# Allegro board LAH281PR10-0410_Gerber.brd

Outline 408.35 x 178.1 mm; copper layers: TOP, GND1, IN1, GND2, IN2, GND3, VCC, IN3, GND4, IN4, GND5, BOTTOM. Coordinates in mm from the lower left corner of the outline.
Outline path: 0,77 1.45,77 arc(1.95,77.51) 1.45,78.01 1.45,81.82 5.41,81.82 arc(8.25,79.8) 11.09,81.82 13.19,81.82 arc(24.8,69.33) 39.94,61.48 arc(45.01,60.3) 50.19,59.9 69.22,59.9 arc(75.64,60.51) 81.84,62.33 arc(90.43,66.92) 97.82,73.27 arc(102.94,80.44) 106.05,88.68 106.05,114.06 arc(106.28,114.63) 106.85,114.86 107.01,114.86 arc(107.58,115.09) 107.81,115.66 107.81,130.06 arc(107.58,130.63) 107.01,130.86 106.85,130.86 arc(106.28,131.09) 106.05,131.66 106.05,158.95 arc(106.34,159.66) 107.05,159.95 110.17,159.95 110.17,178.1 112.72,178.1 112.72,166.9 arc(112.22,166.4) 112.72,165.9 126.52,165.9 arc(127.02,166.4) 126.52,166.9 126.52,178.1 129.65,178.1 129.65,175.55 138.65,175.55 138.65,168.25 arc(138.79,167.9) 139.15,167.75 140.5,167.75 140.5,166.72 arc(140.64,166.37) 141,166.22 150.5,166.22 arc(150.85,166.37) 151,166.72 151,167.75 152.35,167.75 arc(152.7,167.9) 152.85,168.25 152.85,175.55 155.85,175.55 155.85,177.1 170.75,177.1 arc(172.16,176.51) 172.75,175.1 172.75,109.19 185.84,96.1 303.08,96.1 arc(321.92,71.36) 350.63,59.41 360.9,59.41 arc(380.33,64.07) 395.53,77.03 406.35,77.03 arc(407.76,76.44) 408.35,75.03 408.35,67.06 arc(408.28,67.05) 408.2,67.05 406.4,67.05 arc(405.7,66.76) 405.4,66.05 405.4,57.95 arc(405.7,57.24) 406.4,56.95 408.2,56.95 arc(408.28,56.95) 408.35,56.94 408.35,54.4 404.98,54.4 404.98,53.27 396.6,53.27 396.6,45.77 404.98,45.77 404.98,44.65 408.35,44.65 408.35,42.11 arc(408.28,42.1) 408.2,42.1 406.4,42.1 arc(405.7,41.81) 405.4,41.1 405.4,33 arc(405.7,32.29) 406.4,32 408.2,32 arc(408.28,32) 408.35,31.99 408.35,10.3 arc(407.76,8.89) 406.35,8.3 398.85,8.3 arc(397.44,7.71) 396.85,6.3 396.85,2 arc(396.26,0.59) 394.85,0 391.34,0 arc(390.14,0.4) 389.42,1.45 arc(388.6,1.99) 387.95,1.25 385.67,1.25 arc(385.62,1.37) 385.6,1.5 385.6,6.51 arc(385.23,6.99) 384.67,6.76 arc(384.48,6.58) 384.23,6.51 365.77,6.51 arc(365.52,6.58) 365.33,6.76 arc(364.77,6.99) 364.4,6.51 364.4,1.5 arc(364.38,1.37) 364.33,1.25 361.95,1.25 arc(361.3,1.99) 360.48,1.45 arc(359.76,0.4) 358.56,0 11.55,0 arc(10.14,0.59) 9.55,2 9.55,4.3 arc(9.26,5.01) 8.55,5.3 6.55,5.3 arc(5.84,5.59) 5.55,6.3 5.55,7 arc(5.26,7.71) 4.55,8 2.2,8 2.2,38.54 3.85,38.54 3.85,43.78 1.45,43.78 1.45,47.91 arc(1.95,48.4) 1.45,48.9 0,48.9 0,50.35 arc(0.02,50.48) 0.07,50.6 0.43,51.24 arc(0.48,51.36) 0.5,51.49 0.5,58.22 arc(0.48,58.35) 0.43,58.47 0.07,59.1 arc(0.02,59.23) 0,59.35 0,60.15 arc(0.15,60.51) 0.5,60.65 1.04,60.65 1.05,60.66 arc(1.5,61.15) 1.05,61.65 1.05,64.26 arc(1.5,64.76) 1.05,65.25 1.04,65.25 0.5,65.25 arc(0.15,65.4) 0,65.76 0,66.55 arc(0.02,66.68) 0.07,66.8 0.43,67.44 arc(0.48,67.56) 0.5,67.69 0.5,74.42 arc(0.48,74.55) 0.43,74.67 0.07,75.3 arc(0.02,75.43) 0,75.55 0,77

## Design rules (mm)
net group +3.3V_EC_PLL: nets +3.3V_EC_PLL +VSS_PLL
net group BC: nets BC_CLK_ECE1117 BC_DAT_ECE1117
net group CCG5_ILIM1#: nets CCG5_ILIM1# N65693414
net group CCG5_ILIM2#: nets CCG5_ILIM2# N65693416
net group CLK_CNV_PTX_DRX_N: nets CLK_CNV_PTX_DRX_N CLK_CNV_PTX_DRX_N_R
net group CLK_CNV_PTX_DRX_P: nets CLK_CNV_PTX_DRX_P CLK_CNV_PTX_DRX_P_R
net group CNV_COEX1: nets CNV_COEX1 WWAN_COEX1
net group CNV_COEX2: nets CNV_COEX2 WWAN_COEX2
net group CNV_COEX3: nets CNV_COEX3 WWAN_COEX3
net group CPU_24MHZ_R_D: nets CPU_24MHZ_R_D CPU_24MHZ_R_D#
net group CSO_1: nets CSON_1 CSOP_1
net group CSS_1: nets CSSN_1 CSSP_1
net group CSS_2: nets CSSN_2 CSSP_2
net group DDR_XDP_WAN_SMBDAT: nets DDR_XDP_WAN_SMBCLK DDR_XDP_WAN_SMBDAT
net group DIFFPAIR18: nets PCH_DPD_CTRL_CLK PCH_DPD_CTRL_DATA
net group DIFFPAIR67: nets PCIE_PRX_DTX_N19 PCIE_PRX_DTX_P19
net group DIFFPAIR68: nets PCIE_PRX_DTX_N20 PCIE_PRX_DTX_P20
net group DIFFPAIR116: nets TBTB_SBU1 TBTB_SBU2
net group DIFFPAIR117: nets TBTA_SBU1 TBTA_SBU2
net group DIFFPAIR123: nets TBT_B_SBU1 TBT_B_SBU2
net group DIFFPAIR125: nets SW_TBT_A_USB20_N2_R SW_TBT_A_USB20_P2_R
net group DIFFPAIR126: nets TBTB_DPSRC_AUX_N_C TBTB_DPSRC_AUX_P_C
net group DIFFPAIR127: nets TBTA_DPSRC_AUX_N_C TBTA_DPSRC_AUX_P_C
net group INT_SPK_L: nets INT_SPK_L+ INT_SPK_L-
net group INT_SPK_R: nets INT_SPK_R+ INT_SPK_R-
net group INT_SPKR_L: nets INT_SPKR_L+ INT_SPKR_L-
net group INT_SPKR_R: nets INT_SPKR_R+ INT_SPKR_R-
net group MEM_SMBDATA: nets MEM_SMBCLK MEM_SMBDATA
net group MSDATA: nets MSCLK MSDATA
net group PCH_DPB_CTRL_DATA: nets PCH_DPB_CTRL_CLK PCH_DPB_CTRL_DATA
net group PCH_DPC_CTRL_CLK: nets PCH_DPC_CTRL_CLK PCH_DPC_CTRL_DATA
net group PCH_SPI_CLK: nets PCH_SPI_CLK PCH_SPI_CLK_R1
net group PCH_SPI_CS#0: nets PCH_SPI_CS#0 PCH_SPI_CS#0_R1
net group PCH_SPI_CS#1: nets PCH_SPI_CS#1 PCH_SPI_CS#1_R1
net group PCH_SPI_D0: nets PCH_SPI_D0 PCH_SPI_D0_R1
net group PCH_SPI_D1: nets PCH_SPI_D1 PCH_SPI_D1_R1
net group PCH_SPI_D2: nets PCH_SPI_D2 PCH_SPI_D2_R1
net group PCH_SPI_D3: nets PCH_SPI_D3 PCH_SPI_D3_R1
net group PCH_XDP_CLK_DN: nets PCH_XDP_CLK_DN PCH_XDP_CLK_DP
net group PCH_XDP_CLK_DN_R: nets PCH_XDP_CLK_DN_R PCH_XDP_CLK_DP_R
net group PCIE_PRX_C_DTX_N6: nets PCIE_PRX_C_DTX_N6 PCIE_PRX_DTX_N6
net group PCIE_PRX_C_DTX_P6: nets PCIE_PRX_C_DTX_P6 PCIE_PRX_DTX_P6
net group PCIE_PRX_C_RD_DTX_17: nets PCIE_PRX_DTX_N17 PCIE_PRX_DTX_P17
net group PCIE_PRX_C_RD_DTX_18: nets PCIE_PRX_DTX_N18 PCIE_PRX_DTX_P18
net group PCIE_PRX_C_RD_DTX_21: nets PCIE_PRX_DTX_N21 PCIE_PRX_DTX_P21
net group PCIE_PRX_C_RD_DTX_22: nets PCIE_PRX_DTX_N22 PCIE_PRX_DTX_P22
net group PCIE_PRX_C_RD_DTX_23: nets PCIE_PRX_DTX_N23 PCIE_PRX_DTX_P23
net group PCIE_PRX_C_RD_DTX_24: nets PCIE_PRX_DTX_N24 PCIE_PRX_DTX_P24
net group PCIE_PTX_C_DRX_N6: nets PCIE_PTX_C_DRX_N6 PCIE_PTX_DRX_N6
net group PCIE_PTX_C_DRX_N9: nets PCIE_PTX_C_DRX_N9 PCIE_PTX_DRX_N9
net group PCIE_PTX_C_DRX_N10: nets PCIE_PTX_C_DRX_N10 PCIE_PTX_DRX_N10
net group PCIE_PTX_C_DRX_N11: nets PCIE_PTX_C_DRX_N11 PCIE_PTX_DRX_N11
net group PCIE_PTX_C_DRX_N12: nets PCIE_PTX_C_DRX_N12 PCIE_PTX_DRX_N12
net group PCIE_PTX_C_DRX_N13: nets PCIE_PTX_C_DRX_N13 PCIE_PTX_DRX_N13
net group PCIE_PTX_C_DRX_N14: nets PCIE_PTX_C_DRX_N14 PCIE_PTX_DRX_N14
net group PCIE_PTX_C_DRX_N15: nets PCIE_PTX_C_DRX_N15 PCIE_PTX_DRX_N15
net group PCIE_PTX_C_DRX_N16: nets PCIE_PTX_C_DRX_N16 PCIE_PTX_DRX_N16
net group PCIE_PTX_C_DRX_N17: nets PCIE_PTX_C_DRX_N17 PCIE_PTX_DRX_N17
net group PCIE_PTX_C_DRX_N18: nets PCIE_PTX_C_DRX_N18 PCIE_PTX_DRX_N18
net group PCIE_PTX_C_DRX_N19: nets PCIE_PTX_C_DRX_N19 PCIE_PTX_DRX_N19
net group PCIE_PTX_C_DRX_N20: nets PCIE_PTX_C_DRX_N20 PCIE_PTX_DRX_N20
net group PCIE_PTX_C_DRX_N21: nets PCIE_PTX_C_DRX_N21 PCIE_PTX_DRX_N21
net group PCIE_PTX_C_DRX_N22: nets PCIE_PTX_C_DRX_N22 PCIE_PTX_DRX_N22
net group PCIE_PTX_C_DRX_N23: nets PCIE_PTX_C_DRX_N23 PCIE_PTX_DRX_N23
net group PCIE_PTX_C_DRX_N24: nets PCIE_PTX_C_DRX_N24 PCIE_PTX_DRX_N24
net group PCIE_PTX_C_DRX_P6: nets PCIE_PTX_C_DRX_P6 PCIE_PTX_DRX_P6
net group PCIE_PTX_C_DRX_P9: nets PCIE_PTX_C_DRX_P9 PCIE_PTX_DRX_P9
net group PCIE_PTX_C_DRX_P10: nets PCIE_PTX_C_DRX_P10 PCIE_PTX_DRX_P10
net group PCIE_PTX_C_DRX_P11: nets PCIE_PTX_C_DRX_P11 PCIE_PTX_DRX_P11
net group PCIE_PTX_C_DRX_P12: nets PCIE_PTX_C_DRX_P12 PCIE_PTX_DRX_P12
net group PCIE_PTX_C_DRX_P13: nets PCIE_PTX_C_DRX_P13 PCIE_PTX_DRX_P13
net group PCIE_PTX_C_DRX_P14: nets PCIE_PTX_C_DRX_P14 PCIE_PTX_DRX_P14
net group PCIE_PTX_C_DRX_P15: nets PCIE_PTX_C_DRX_P15 PCIE_PTX_DRX_P15
net group PCIE_PTX_C_DRX_P16: nets PCIE_PTX_C_DRX_P16 PCIE_PTX_DRX_P16
net group PCIE_PTX_C_DRX_P17: nets PCIE_PTX_C_DRX_P17 PCIE_PTX_DRX_P17
net group PCIE_PTX_C_DRX_P18: nets PCIE_PTX_C_DRX_P18 PCIE_PTX_DRX_P18
net group PCIE_PTX_C_DRX_P19: nets PCIE_PTX_C_DRX_P19 PCIE_PTX_DRX_P19
net group PCIE_PTX_C_DRX_P20: nets PCIE_PTX_C_DRX_P20 PCIE_PTX_DRX_P20
net group PCIE_PTX_C_DRX_P21: nets PCIE_PTX_C_DRX_P21 PCIE_PTX_DRX_P21
net group PCIE_PTX_C_DRX_P22: nets PCIE_PTX_C_DRX_P22 PCIE_PTX_DRX_P22
net group PCIE_PTX_C_DRX_P23: nets PCIE_PTX_C_DRX_P23 PCIE_PTX_DRX_P23
net group PCIE_PTX_C_DRX_P24: nets PCIE_PTX_C_DRX_P24 PCIE_PTX_DRX_P24
net group REFCLK_CNV: nets N65699658 REFCLK_CNV
net group SD_1_D0: nets SD_1_D0 SD_1_D1
net group SD_1_D1_R: nets SD_1_D0_R SD_1_D1_R
net group SML0_SMBDATA: nets SML0_SMBCLK SML0_SMBDATA
net group SML1_SMBDATA: nets SML1_SMBCLK SML1_SMBDATA
net group SR_1: nets SRN_1 SRP_1
net group SW2_DP2_2_AUXN: nets SW2_DP2_2_AUXN SW2_DP2_2_AUXP
net group SW3_DP1_AUXN: nets SW3_DP1_AUXN SW3_DP1_AUXN_C
net group SW3_DP1_AUXP: nets SW3_DP1_AUXP SW3_DP1_AUXP_C
net group SW3_DP1_N0: nets SW3_DP1_N0 SW3_DP1_N0_C
net group SW3_DP1_N1: nets SW3_DP1_N1 SW3_DP1_N1_C
net group SW3_DP1_N2: nets SW3_DP1_N2 SW3_DP1_N2_C
net group SW3_DP1_N3: nets SW3_DP1_N3 SW3_DP1_N3_C
net group SW3_DP1_P0: nets SW3_DP1_P0 SW3_DP1_P0_C
net group SW3_DP1_P1: nets SW3_DP1_P1 SW3_DP1_P1_C
net group SW3_DP1_P2: nets SW3_DP1_P2 SW3_DP1_P2_C
net group SW3_DP1_P3: nets SW3_DP1_P3 SW3_DP1_P3_C
net group SW4_DP2_AUXN: nets SW4_DP2_AUXN SW4_DP2_AUXN_C
net group SW4_DP2_AUXP: nets SW4_DP2_AUXP SW4_DP2_AUXP_C
net group SW4_DP2_N0: nets SW4_DP2_N0 SW4_DP2_N0_C
net group SW4_DP2_N1: nets SW4_DP2_N1 SW4_DP2_N1_C
net group SW4_DP2_N2: nets SW4_DP2_N2 SW4_DP2_N2_C
net group SW4_DP2_N3: nets SW4_DP2_N3 SW4_DP2_N3_C
net group SW4_DP2_P0: nets SW4_DP2_P0 SW4_DP2_P0_C
net group SW4_DP2_P1: nets SW4_DP2_P1 SW4_DP2_P1_C
net group SW4_DP2_P2: nets SW4_DP2_P2 SW4_DP2_P2_C
net group SW4_DP2_P3: nets SW4_DP2_P3 SW4_DP2_P3_C
net group TBT_A_TRX_DTX_N1: nets TBT_A_TRX_DTX_N1 TBT_A_TRX_DTX_N1_R
net group TBT_A_TRX_DTX_N2: nets TBT_A_TRX_DTX_N2 TBT_A_TRX_DTX_N2_R
net group TBT_A_TRX_DTX_P1: nets TBT_A_TRX_DTX_P1 TBT_A_TRX_DTX_P1_R
net group TBT_A_TRX_DTX_P2: nets TBT_A_TRX_DTX_P2 TBT_A_TRX_DTX_P2_R
net group TBT_B_TRX_DTX_N1: nets TBT_B_TRX_DTX_N1 TBT_B_TRX_DTX_N1_R
net group TBT_B_TRX_DTX_N2: nets TBT_B_TRX_DTX_N2 TBT_B_TRX_DTX_N2_R
net group TBT_B_TRX_DTX_P1: nets TBT_B_TRX_DTX_P1 TBT_B_TRX_DTX_P1_R
net group TBT_B_TRX_DTX_P2: nets TBT_B_TRX_DTX_P2 TBT_B_TRX_DTX_P2_R
net group UART2RXD: nets UART2_RXD UART2RXD
net group UART2TXD: nets UART2_TXD UART2TXD
net group USB20_6: nets USB20_N6 USB20_P6
net group XTAL24_IN_R: nets XTAL24_IN_R XTAL24_IN_R1
net group XTAL24_OUT: nets XTAL24_OUT XTAL24_OUT_R1
net group CCG5_SMBCLK: nets CCG5_SMBCLK N65694331 N65695150
net group CCG5_SMBDAT: nets CCG5_SMBDAT N65694363 N65695146
net group CL_SIG: nets PCH_CL_CLK1 PCH_CL_DATA1 PCH_CL_RST1#
net group DDR_A_CLK: nets DDR_A_CLK0 DDR_A_CLK1 DDR_A_CLK2 DDR_A_CLK3 DDR_A_CLK#0 DDR_A_CLK#1 DDR_A_CLK#2 DDR_A_CLK#3
net group DDR_A_CMD: nets DDR_A_ACT# DDR_A_BA0 DDR_A_BA1 DDR_A_BG0 DDR_A_BG1 DDR_A_MA0 DDR_A_MA1 DDR_A_MA2 DDR_A_MA3 DDR_A_MA4 DDR_A_MA5 DDR_A_MA6 DDR_A_MA7 DDR_A_MA8 DDR_A_MA9 DDR_A_MA10 DDR_A_MA11 DDR_A_MA12 DDR_A_MA13 DDR_A_MA14 DDR_A_MA15 DDR_A_MA16 DDR_A_PARITY
net group DDR_A_CTL: nets DDR_A_CKE0 DDR_A_CKE1 DDR_A_CKE2 DDR_A_CKE3 DDR_A_CS#0 DDR_A_CS#1 DDR_A_CS#2 DDR_A_CS#3 DDR_A_ODT0 DDR_A_ODT1 DDR_A_ODT2 DDR_A_ODT3
net group DDR_A_D0: nets DDR_A_D0 DDR_A_D1 DDR_A_D2 DDR_A_D3 DDR_A_D4 DDR_A_D5 DDR_A_D6 DDR_A_D7
net group DDR_A_D1: nets DDR_A_D8 DDR_A_D9 DDR_A_D10 DDR_A_D11 DDR_A_D12 DDR_A_D13 DDR_A_D14 DDR_A_D15
net group DDR_A_D2: nets DDR_A_D16 DDR_A_D17 DDR_A_D18 DDR_A_D19 DDR_A_D20 DDR_A_D21 DDR_A_D22 DDR_A_D23
net group DDR_A_D3: nets DDR_A_D24 DDR_A_D25 DDR_A_D26 DDR_A_D27 DDR_A_D28 DDR_A_D29 DDR_A_D30 DDR_A_D31
net group DDR_A_D4: nets DDR_A_D32 DDR_A_D33 DDR_A_D34 DDR_A_D35 DDR_A_D36 DDR_A_D37 DDR_A_D38 DDR_A_D39
net group DDR_A_D5: nets DDR_A_D40 DDR_A_D41 DDR_A_D42 DDR_A_D43 DDR_A_D44 DDR_A_D45 DDR_A_D46 DDR_A_D47
net group DDR_A_D6: nets DDR_A_D48 DDR_A_D49 DDR_A_D50 DDR_A_D51 DDR_A_D52 DDR_A_D53 DDR_A_D54 DDR_A_D55
net group DDR_A_D7: nets DDR_A_D56 DDR_A_D57 DDR_A_D58 DDR_A_D59 DDR_A_D60 DDR_A_D61 DDR_A_D62 DDR_A_D63
net group DDR_A_DQS: nets DDR_A_DQS0 DDR_A_DQS1 DDR_A_DQS2 DDR_A_DQS3 DDR_A_DQS4 DDR_A_DQS5 DDR_A_DQS6 DDR_A_DQS7 DDR_A_DQS8 DDR_A_DQS#0 DDR_A_DQS#1 DDR_A_DQS#2 DDR_A_DQS#3 DDR_A_DQS#4 DDR_A_DQS#5 DDR_A_DQS#6 DDR_A_DQS#7 DDR_A_DQS#8
net group DDR_A_ECC: nets DDR_A_CB0 DDR_A_CB1 DDR_A_CB2 DDR_A_CB3 DDR_A_CB4 DDR_A_CB5 DDR_A_CB6 DDR_A_CB7
net group DDR_B_CLK: nets DDR_B_CLK0 DDR_B_CLK1 DDR_B_CLK2 DDR_B_CLK3 DDR_B_CLK#0 DDR_B_CLK#1 DDR_B_CLK#2 DDR_B_CLK#3
net group DDR_B_CMD: nets DDR_B_ACT# DDR_B_BA0 DDR_B_BA1 DDR_B_BG0 DDR_B_BG1 DDR_B_MA0 DDR_B_MA1 DDR_B_MA2 DDR_B_MA3 DDR_B_MA4 DDR_B_MA5 DDR_B_MA6 DDR_B_MA7 DDR_B_MA8 DDR_B_MA9 DDR_B_MA10 DDR_B_MA11 DDR_B_MA12 DDR_B_MA13 DDR_B_MA14 DDR_B_MA15 DDR_B_MA16 DDR_B_PARITY
net group DDR_B_CTL: nets DDR_B_CKE0 DDR_B_CKE1 DDR_B_CKE2 DDR_B_CKE3 DDR_B_CS#0 DDR_B_CS#1 DDR_B_CS#2 DDR_B_CS#3 DDR_B_ODT0 DDR_B_ODT1 DDR_B_ODT2 DDR_B_ODT3
net group DDR_B_D0: nets DDR_B_D0 DDR_B_D1 DDR_B_D2 DDR_B_D3 DDR_B_D4 DDR_B_D5 DDR_B_D6 DDR_B_D7
net group DDR_B_D1: nets DDR_B_D8 DDR_B_D9 DDR_B_D10 DDR_B_D11 DDR_B_D12 DDR_B_D13 DDR_B_D14 DDR_B_D15
net group DDR_B_D2: nets DDR_B_D16 DDR_B_D17 DDR_B_D18 DDR_B_D19 DDR_B_D20 DDR_B_D21 DDR_B_D22 DDR_B_D23
net group DDR_B_D3: nets DDR_B_D24 DDR_B_D25 DDR_B_D26 DDR_B_D27 DDR_B_D28 DDR_B_D29 DDR_B_D30 DDR_B_D31
net group DDR_B_D4: nets DDR_B_D32 DDR_B_D33 DDR_B_D34 DDR_B_D35 DDR_B_D36 DDR_B_D37 DDR_B_D38 DDR_B_D39
net group DDR_B_D5: nets DDR_B_D40 DDR_B_D41 DDR_B_D42 DDR_B_D43 DDR_B_D44 DDR_B_D45 DDR_B_D46 DDR_B_D47
net group DDR_B_D6: nets DDR_B_D48 DDR_B_D49 DDR_B_D50 DDR_B_D51 DDR_B_D52 DDR_B_D53 DDR_B_D54 DDR_B_D55
net group DDR_B_D7: nets DDR_B_D56 DDR_B_D57 DDR_B_D58 DDR_B_D59 DDR_B_D60 DDR_B_D61 DDR_B_D62 DDR_B_D63
net group DDR_B_DQS: nets DDR_B_DQS0 DDR_B_DQS1 DDR_B_DQS2 DDR_B_DQS3 DDR_B_DQS4 DDR_B_DQS5 DDR_B_DQS6 DDR_B_DQS7 DDR_B_DQS8 DDR_B_DQS#0 DDR_B_DQS#1 DDR_B_DQS#2 DDR_B_DQS#3 DDR_B_DQS#4 DDR_B_DQS#5 DDR_B_DQS#6 DDR_B_DQS#7 DDR_B_DQS#8
net group DDR_B_ECC: nets DDR_B_CB0 DDR_B_CB1 DDR_B_CB2 DDR_B_CB3 DDR_B_CB4 DDR_B_CB5 DDR_B_CB6 DDR_B_CB7
net group DEMUX_PS8331: nets SW1_EDP_AUXN SW1_EDP_AUXN_C SW1_EDP_AUXP SW1_EDP_AUXP_C SW2_DP2_1_AUXN SW2_DP2_1_AUXN_C SW2_DP2_1_AUXP SW2_DP2_1_AUXP_C SW2_DP2_1_N0 SW2_DP2_1_N0_C SW2_DP2_1_N1 SW2_DP2_1_N1_C SW2_DP2_1_N2 SW2_DP2_1_N2_C SW2_DP2_1_N3 SW2_DP2_1_N3_C SW2_DP2_1_P0 SW2_DP2_1_P0_C SW2_DP2_1_P1 SW2_DP2_1_P1_C SW2_DP2_1_P2 SW2_DP2_1_P2_C SW2_DP2_1_P3 SW2_DP2_1_P3_C SW2_DP2_2_N0 SW2_DP2_2_N1 SW2_DP2_2_N2 SW2_DP2_2_N3 SW2_DP2_2_P0 SW2_DP2_2_P1 SW2_DP2_2_P2 SW2_DP2_2_P3
net group DIFF_CLK: nets CLK_CNV_PRX_DTX_N CLK_CNV_PRX_DTX_P CLK_PCIE_N1 CLK_PCIE_N2 CLK_PCIE_N3 CLK_PCIE_N4 CLK_PCIE_N6 CLK_PCIE_N7 CLK_PCIE_N8 CLK_PCIE_N9 CLK_PCIE_N10 CLK_PCIE_P1 CLK_PCIE_P2 CLK_PCIE_P3 CLK_PCIE_P4 CLK_PCIE_P6 CLK_PCIE_P7 CLK_PCIE_P8 CLK_PCIE_P9 CLK_PCIE_P10 CLK_PEG_N0 CLK_PEG_P0 PCH_CPU_BCLK_D PCH_CPU_BCLK_D# PCH_CPU_BCLK_R_D PCH_CPU_BCLK_R_D# PCH_CPU_NSSC_CLK_D PCH_CPU_NSSC_CLK_D# PCH_CPU_PCIBCLK_D PCH_CPU_PCIBCLK_D# PCH_CPU_PCIBCLK_R_D PCH_CPU_PCIBCLK_R_D#
net group DIFFPAIR115: nets N28153073
net group DMI_RX: nets DMI_CTX_PRX_N0 DMI_CTX_PRX_N1 DMI_CTX_PRX_N2 DMI_CTX_PRX_N3 DMI_CTX_PRX_P0 DMI_CTX_PRX_P1 DMI_CTX_PRX_P2 DMI_CTX_PRX_P3
net group DMI_TX: nets DMI_CRX_PTX_N0 DMI_CRX_PTX_N1 DMI_CRX_PTX_N2 DMI_CRX_PTX_N3 DMI_CRX_PTX_P0 DMI_CRX_PTX_P1 DMI_CRX_PTX_P2 DMI_CRX_PTX_P3
net group EDP: nets EDP_AUXN EDP_AUXN_C EDP_AUXP EDP_AUXP_C EDP_TXN0 EDP_TXN0_C EDP_TXN1 EDP_TXN1_C EDP_TXN2 EDP_TXN2_C EDP_TXN3 EDP_TXN3_C EDP_TXP0 EDP_TXP0_C EDP_TXP1 EDP_TXP1_C EDP_TXP2 EDP_TXP2_C EDP_TXP3 EDP_TXP3_C
net group INTEL_DDI: nets CPU_DP1_AUXN CPU_DP1_AUXN_C CPU_DP1_AUXP CPU_DP1_AUXP_C CPU_DP1_N0 CPU_DP1_N0_C CPU_DP1_N1 CPU_DP1_N1_C CPU_DP1_N2 CPU_DP1_N2_C CPU_DP1_N3 CPU_DP1_N3_C CPU_DP1_P0 CPU_DP1_P0_C CPU_DP1_P1 CPU_DP1_P1_C CPU_DP1_P2 CPU_DP1_P2_C CPU_DP1_P3 CPU_DP1_P3_C CPU_DP2_AUXN CPU_DP2_AUXN_C CPU_DP2_AUXP CPU_DP2_AUXP_C CPU_DP2_N0 CPU_DP2_N0_C CPU_DP2_N1 CPU_DP2_N1_C CPU_DP2_N2 CPU_DP2_N2_C CPU_DP2_N3 CPU_DP2_N3_C CPU_DP2_P0 CPU_DP2_P0_C CPU_DP2_P1 CPU_DP2_P1_C CPU_DP2_P2 CPU_DP2_P2_C CPU_DP2_P3 CPU_DP2_P3_C CPU_DP3_AUXN CPU_DP3_AUXP CPU_DP3_N0 CPU_DP3_N1 CPU_DP3_N2 CPU_DP3_N3 CPU_DP3_P0 CPU_DP3_P1 CPU_DP3_P2 CPU_DP3_P3
net group LAN: nets LAN_MDIN0 LAN_MDIN0_L LAN_MDIN1 LAN_MDIN1_L LAN_MDIN2 LAN_MDIN2_L LAN_MDIN3 LAN_MDIN3_L LAN_MDIP0 LAN_MDIP0_L LAN_MDIP1 LAN_MDIP1_L LAN_MDIP2 LAN_MDIP2_L LAN_MDIP3 LAN_MDIP3_L
net group LAN-NOREF: nets RJ45_MDIN0 RJ45_MDIN1 RJ45_MDIN2 RJ45_MDIN3 RJ45_MDIP0 RJ45_MDIP1 RJ45_MDIP2 RJ45_MDIP3
net group MUXPSB331: nets SW1_EDP_N0 SW1_EDP_N0_C SW1_EDP_N1 SW1_EDP_N1_C SW1_EDP_N2 SW1_EDP_N2_C SW1_EDP_N3 SW1_EDP_N3_C SW1_EDP_P0 SW1_EDP_P1 SW1_EDP_P1_C SW1_EDP_P2 SW1_EDP_P2_C SW1_EDP_P3 SW1_EDP_P3_C
net group MXM_DDI: nets GPU_DP1_AUXN GPU_DP1_AUXP GPU_DP1_C_AUXN GPU_DP1_C_AUXP GPU_DP1_N0 GPU_DP1_N0_C GPU_DP1_N1 GPU_DP1_N1_C GPU_DP1_N2 GPU_DP1_N2_C GPU_DP1_N3 GPU_DP1_N3_C GPU_DP1_P0 GPU_DP1_P0_C GPU_DP1_P1 GPU_DP1_P1_C GPU_DP1_P2 GPU_DP1_P2_C GPU_DP1_P3 GPU_DP1_P3_C GPU_DP2_AUXN GPU_DP2_AUXP GPU_DP2_C_AUXN GPU_DP2_C_AUXP GPU_DP2_N0 GPU_DP2_N0_C GPU_DP2_N1 GPU_DP2_N1_C GPU_DP2_N2 GPU_DP2_N2_C GPU_DP2_N3 GPU_DP2_N3_C GPU_DP2_P0 GPU_DP2_P0_C GPU_DP2_P1 GPU_DP2_P1_C GPU_DP2_P2 GPU_DP2_P2_C GPU_DP2_P3 GPU_DP2_P3_C GPU_EDP_AUXN GPU_EDP_AUXN_C GPU_EDP_AUXP GPU_EDP_AUXP_C GPU_EDP_N0 GPU_EDP_N0_C GPU_EDP_N1 GPU_EDP_N1_C GPU_EDP_N2 GPU_EDP_N2_C GPU_EDP_N3 GPU_EDP_N3_C GPU_EDP_P0 GPU_EDP_P0_C GPU_EDP_P1 GPU_EDP_P1_C GPU_EDP_P2 GPU_EDP_P2_C GPU_EDP_P3 GPU_EDP_P3_C
net group OTHER: nets CPU_2_PCH_TRIGGER_R H_CATERR# H_PWRGD H_THERMTRIP# PCH_2_CPU_TRIGGER PLTRST_CPU# PROCHOT# VCCST_PWRGD
net group PCH_PLTRST#: nets PCH_PLTRST# PLTRST_GPU# PLTRST_LAN# PLTRST_TPM#
net group PCIE_RX: nets PCIE_PRX_C_DTX_N5 PCIE_PRX_C_DTX_P5 PCIE_PRX_C_TTX_N1 PCIE_PRX_C_TTX_N2 PCIE_PRX_C_TTX_N3 PCIE_PRX_C_TTX_N4 PCIE_PRX_C_TTX_P1 PCIE_PRX_C_TTX_P2 PCIE_PRX_C_TTX_P3 PCIE_PRX_C_TTX_P4 PCIE_PRX_DTX_N5 PCIE_PRX_DTX_N7 PCIE_PRX_DTX_N8 PCIE_PRX_DTX_N10 PCIE_PRX_DTX_N11 PCIE_PRX_DTX_N12 PCIE_PRX_DTX_N14 PCIE_PRX_DTX_N15 PCIE_PRX_DTX_N16 PCIE_PRX_DTX_P5 PCIE_PRX_DTX_P7 PCIE_PRX_DTX_P8 PCIE_PRX_DTX_P10 PCIE_PRX_DTX_P11 PCIE_PRX_DTX_P12 PCIE_PRX_DTX_P14 PCIE_PRX_DTX_P15 PCIE_PRX_DTX_P16 PCIE_PRX_TTX_N1 PCIE_PRX_TTX_N2 PCIE_PRX_TTX_N3 PCIE_PRX_TTX_N4 PCIE_PRX_TTX_P1 PCIE_PRX_TTX_P2 PCIE_PRX_TTX_P3 PCIE_PRX_TTX_P4 PCIE_PTX_C_DRX_N5 PCIE_PTX_C_DRX_N7 PCIE_PTX_C_DRX_N8 PCIE_PTX_C_DRX_P5 PCIE_PTX_C_DRX_P7 PCIE_PTX_C_DRX_P8 PCIE_PTX_C_TRX_N1 PCIE_PTX_C_TRX_N2 PCIE_PTX_C_TRX_N3 PCIE_PTX_C_TRX_N4 PCIE_PTX_C_TRX_P1 PCIE_PTX_C_TRX_P2 PCIE_PTX_C_TRX_P3 PCIE_PTX_C_TRX_P4 PCIE_PTX_DRX_N5 PCIE_PTX_DRX_N7 PCIE_PTX_DRX_N8 PCIE_PTX_DRX_P5 PCIE_PTX_DRX_P7 PCIE_PTX_DRX_P8 PCIE_PTX_TRX_N1 PCIE_PTX_TRX_N2 PCIE_PTX_TRX_N3 PCIE_PTX_TRX_N4 PCIE_PTX_TRX_P1 PCIE_PTX_TRX_P2 PCIE_PTX_TRX_P3 PCIE_PTX_TRX_P4
net group PEG_RX: nets PEG_CTX_C_GRX_N0 PEG_CTX_C_GRX_N1 PEG_CTX_C_GRX_N2 PEG_CTX_C_GRX_N3 PEG_CTX_C_GRX_N4 PEG_CTX_C_GRX_N5 PEG_CTX_C_GRX_N6 PEG_CTX_C_GRX_N7 PEG_CTX_C_GRX_N8 PEG_CTX_C_GRX_N9 PEG_CTX_C_GRX_N10 PEG_CTX_C_GRX_N11 PEG_CTX_C_GRX_N12 PEG_CTX_C_GRX_N13 PEG_CTX_C_GRX_N14 PEG_CTX_C_GRX_N15 PEG_CTX_C_GRX_P0 PEG_CTX_C_GRX_P1 PEG_CTX_C_GRX_P2 PEG_CTX_C_GRX_P3 PEG_CTX_C_GRX_P4 PEG_CTX_C_GRX_P5 PEG_CTX_C_GRX_P6 PEG_CTX_C_GRX_P7 PEG_CTX_C_GRX_P8 PEG_CTX_C_GRX_P9 PEG_CTX_C_GRX_P10 PEG_CTX_C_GRX_P11 PEG_CTX_C_GRX_P12 PEG_CTX_C_GRX_P13 PEG_CTX_C_GRX_P14 PEG_CTX_C_GRX_P15 PEG_CTX_GRX_N0 PEG_CTX_GRX_N1 PEG_CTX_GRX_N2 PEG_CTX_GRX_N3 PEG_CTX_GRX_N4 PEG_CTX_GRX_N5 PEG_CTX_GRX_N6 PEG_CTX_GRX_N7 PEG_CTX_GRX_N8 PEG_CTX_GRX_N9 PEG_CTX_GRX_N10 PEG_CTX_GRX_N11 PEG_CTX_GRX_N12 PEG_CTX_GRX_N13 PEG_CTX_GRX_N14 PEG_CTX_GRX_N15 PEG_CTX_GRX_P0 PEG_CTX_GRX_P1 PEG_CTX_GRX_P2 PEG_CTX_GRX_P3 PEG_CTX_GRX_P4 PEG_CTX_GRX_P5 PEG_CTX_GRX_P6 PEG_CTX_GRX_P7 PEG_CTX_GRX_P8 PEG_CTX_GRX_P9 PEG_CTX_GRX_P10 PEG_CTX_GRX_P11 PEG_CTX_GRX_P12 PEG_CTX_GRX_P13 PEG_CTX_GRX_P14 PEG_CTX_GRX_P15
net group PEG_TX: nets PEG_CRX_C_GTX_N0 PEG_CRX_C_GTX_N1 PEG_CRX_C_GTX_N2 PEG_CRX_C_GTX_N3 PEG_CRX_C_GTX_N4 PEG_CRX_C_GTX_N5 PEG_CRX_C_GTX_N6 PEG_CRX_C_GTX_N7 PEG_CRX_C_GTX_N8 PEG_CRX_C_GTX_N9 PEG_CRX_C_GTX_N10 PEG_CRX_C_GTX_N11 PEG_CRX_C_GTX_N12 PEG_CRX_C_GTX_N13 PEG_CRX_C_GTX_N14 PEG_CRX_C_GTX_N15 PEG_CRX_C_GTX_P0 PEG_CRX_C_GTX_P1 PEG_CRX_C_GTX_P2 PEG_CRX_C_GTX_P3 PEG_CRX_C_GTX_P4 PEG_CRX_C_GTX_P5 PEG_CRX_C_GTX_P6 PEG_CRX_C_GTX_P7 PEG_CRX_C_GTX_P8 PEG_CRX_C_GTX_P9 PEG_CRX_C_GTX_P10 PEG_CRX_C_GTX_P11 PEG_CRX_C_GTX_P12 PEG_CRX_C_GTX_P13 PEG_CRX_C_GTX_P14 PEG_CRX_C_GTX_P15 PEG_CRX_GTX_N0 PEG_CRX_GTX_N1 PEG_CRX_GTX_N2 PEG_CRX_GTX_N3 PEG_CRX_GTX_N4 PEG_CRX_GTX_N5 PEG_CRX_GTX_N6 PEG_CRX_GTX_N7 PEG_CRX_GTX_N8 PEG_CRX_GTX_N9 PEG_CRX_GTX_N10 PEG_CRX_GTX_N11 PEG_CRX_GTX_N12 PEG_CRX_GTX_N13 PEG_CRX_GTX_N14 PEG_CRX_GTX_N15 PEG_CRX_GTX_P0 PEG_CRX_GTX_P1 PEG_CRX_GTX_P2 PEG_CRX_GTX_P3 PEG_CRX_GTX_P4 PEG_CRX_GTX_P5 PEG_CRX_GTX_P6 PEG_CRX_GTX_P7 PEG_CRX_GTX_P8 PEG_CRX_GTX_P9 PEG_CRX_GTX_P10 PEG_CRX_GTX_P11 PEG_CRX_GTX_P12 PEG_CRX_GTX_P13 PEG_CRX_GTX_P14 PEG_CRX_GTX_P15
net group POWER: nets +0.6V_P +0.9V_LAN +1.2V_RUN_PWR +3.3V_SSD3_PWR +3.3V_SSD4_PWR +3.3V_SSD5_PWR +3.3V_SSD6_PWR +3.3V_TBT +5V_ALWP +5V_USB_PWR1 +5V_USB_PWR2 +5V_USB_PWR3 +5V_VBUS1 +5V_VBUS2 +19VB_1.2V +19VB_1V +19VB_3V +19VB_3VR +19VB_5V +19VB_5VR +19VB_IO +DGFF_PWR_SRC +VCC_SFR_OC LX_1.2V LX_+1VSP LX_CHG VDD12_A VDD12_B VDD33_A VDD33_B VDD_1.2V VDDA12_A VDDA12_B VDDP_1.2V VDDRX12_A VDDRX12_B VDDTX12_A VDDTX12_B
net group RTC_SIG: nets PCH_RTCRST# PCH_RTCX1 PCH_RTCX1_R PCH_RTCX2 SRTCRST#
net group S15: nets REM_DIODE1_N REM_DIODE1_P REM_DIODE2_N REM_DIODE2_P REM_DIODE3_N REM_DIODE3_P REM_DIODE4_N REM_DIODE4_P
net group SATA: nets PCIE_PRX_DTX_N9 PCIE_PRX_DTX_N13 PCIE_PRX_DTX_P9 PCIE_PRX_DTX_P13
net group SD: nets SD_1_CD# SD_1_CLK SD_1_CLK_R SD_1_CMD SD_1_CMD_R SD_1_D2 SD_1_D2_R SD_1_D3 SD_1_D3_R SDWP_Q
net group SD-DIFF: nets SD_1_N0 SD_1_N1 SD_1_P0 SD_1_P1
net group SPI: nets PCH_SPI_CLK_0_R PCH_SPI_CLK_1_R PCH_SPI_CLK_2_R PCH_SPI_CS#0_R2 PCH_SPI_CS#2 PCH_SPI_CS#2_R PCH_SPI_D0_0_R PCH_SPI_D0_2_R PCH_SPI_D1_0_R PCH_SPI_D1_2_R PCH_SPI_D2_0_R PCH_SPI_D2_XDP PCH_SPI_D3_0_R
net group SW1_EDP_N0_C: nets SW1_EDP_P0_C
net group TBT-A: nets TBT_A_TTX_C_DRX_N1 TBT_A_TTX_C_DRX_N2 TBT_A_TTX_C_DRX_P1 TBT_A_TTX_C_DRX_P2 TBT_A_TTX_DRX_N1 TBT_A_TTX_DRX_N2 TBT_A_TTX_DRX_P1 TBT_A_TTX_DRX_P2
net group TBT-ADIFF: nets SW_TBT_A_USB20_N1 SW_TBT_A_USB20_N1_R SW_TBT_A_USB20_N2 SW_TBT_A_USB20_P1 SW_TBT_A_USB20_P1_R SW_TBT_A_USB20_P2 TBT_A_SBU1 TBT_A_SBU2
net group TBT-B: nets TBT_B_TTX_C_DRX_N1 TBT_B_TTX_C_DRX_N2 TBT_B_TTX_C_DRX_P1 TBT_B_TTX_C_DRX_P2 TBT_B_TTX_DRX_N1 TBT_B_TTX_DRX_N2 TBT_B_TTX_DRX_P1 TBT_B_TTX_DRX_P2
net group TBT-BDIFF: nets SW_TBT_B_USB20_N1 SW_TBT_B_USB20_N1_R SW_TBT_B_USB20_N2 SW_TBT_B_USB20_N2_R SW_TBT_B_USB20_P1 SW_TBT_B_USB20_P1_R SW_TBT_B_USB20_P2 SW_TBT_B_USB20_P2_R
net group TBT_A_USB20N: nets TBT_A_USB20N USB20_N4 USB20_NA
net group TBT_A_USB20P: nets TBT_A_USB20P USB20_P4 USB20_PA
net group TBT_B_USB20N: nets TBT_B_USB20N USB20_N5 USB20_NB
net group TBT_B_USB20P: nets TBT_B_USB20P USB20_P5 USB20_PB
net group USB2: nets CHR_USB20_N1 CHR_USB20_N2 CHR_USB20_N3 CHR_USB20_P1 CHR_USB20_P2 CHR_USB20_P3 USB20_N1 USB20_N1_R USB20_N2 USB20_N2_R USB20_N3 USB20_N3_R USB20_N8 USB20_N10 USB20_N11 USB20_N11_R USB20_N14 USB20_N14_R USB20_P1 USB20_P1_R USB20_P2 USB20_P2_R USB20_P3 USB20_P3_R USB20_P8 USB20_P10 USB20_P11 USB20_P11_R USB20_P14 USB20_P14_R
net group USB3: nets USB3_PRX_C_RD_DTX_N1 USB3_PRX_C_RD_DTX_N3 USB3_PRX_C_RD_DTX_P1 USB3_PRX_C_RD_DTX_P3 USB3_PRX_DTX_N1 USB3_PRX_DTX_N2 USB3_PRX_DTX_N3 USB3_PRX_DTX_N4 USB3_PRX_DTX_P1 USB3_PRX_DTX_P2 USB3_PRX_DTX_P3 USB3_PRX_DTX_P4 USB3_PRX_L_DTX_N2 USB3_PRX_L_DTX_P2 USB3_PRX_RD_DTX_N1 USB3_PRX_RD_DTX_N3 USB3_PRX_RD_DTX_P1 USB3_PRX_RD_DTX_P3 USB3_PTX_C_DRX_N1 USB3_PTX_C_DRX_N2 USB3_PTX_C_DRX_N3 USB3_PTX_C_DRX_N4 USB3_PTX_C_DRX_P1 USB3_PTX_C_DRX_P2 USB3_PTX_C_DRX_P3 USB3_PTX_C_DRX_P4 USB3_PTX_C_RD_DRX_N1 USB3_PTX_C_RD_DRX_N3 USB3_PTX_C_RD_DRX_P1 USB3_PTX_C_RD_DRX_P3 USB3_PTX_DRX_N1 USB3_PTX_DRX_N2 USB3_PTX_DRX_N3 USB3_PTX_DRX_N4 USB3_PTX_DRX_P1 USB3_PTX_DRX_P2 USB3_PTX_DRX_P3 USB3_PTX_DRX_P4 USB3_PTX_L_DRX_N2 USB3_PTX_L_DRX_P2 USB3_PTX_RD_DRX_N1 USB3_PTX_RD_DRX_N3 USB3_PTX_RD_DRX_P1 USB3_PTX_RD_DRX_P3
net group WLAN: nets CNV_PRX_DTX_N0 CNV_PRX_DTX_N1 CNV_PRX_DTX_P0 CNV_PRX_DTX_P1 CNV_PTX_C_DRX_N0 CNV_PTX_C_DRX_N1 CNV_PTX_C_DRX_P0 CNV_PTX_C_DRX_P1 CNV_PTX_DRX_N0 CNV_PTX_DRX_N1 CNV_PTX_DRX_P0 CNV_PTX_DRX_P1
nets with their own width: min track width 0.14; nets DDR_A_DRAMRST# DDR_B_DRAMRST#
nets with their own width: min track width 0.254; nets +RTC_CELL_VBAT
nets with their own width: min track width 0.305; nets DDR_RCOMP0 DDR_RCOMP1 DDR_RCOMP2
nets with their own width: min track width 0.381; nets +1.0V_AZPLL
nets with their own width: min track width 0.508; nets +3.3V_ALW_R +3.3V_SPI +DDR_VREF_B_DQ +V_DDR_REFCA_A +V_DDR_REFCA_B

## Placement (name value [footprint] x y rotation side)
C190  10U_0402_6.3V6M  [C_0402]  144.17 104.66 180 top
C191  10U_0402_6.3V6M  [C_0402]  167.02 134.84 270 bottom
C192  470P_0402_50V7K  [C_0402]  148.51 107.23 270 top
C193  470P_0402_50V7K  [C_0402]  147.62 107.23 270 top
C194  10U_0402_6.3V6M  [C_0402]  151.83 104.28 0 top
C195  470P_0402_50V7K  [C_0402]  168.14 135.5 270 bottom
C199  10U_0402_6.3V6M  [C_0402]  128.09 85.09 90 bottom
C200  10U_0402_6.3V6M  [C_0402]  331.61 17.29 0 top
C201  470P_0402_50V7K  [C_0402]  329.69 20.46 0 top
C202  470P_0402_50V7K  [C_0402]  329.69 19.45 0 top
C203  10U_0402_6.3V6M  [C_0402]  332.74 22.24 0 top
C206  10U_0402_6.3V6M  [C_0402]  353.72 10.56 180 bottom
C207  470P_0402_50V7K  [C_0402]  355.47 13.6 0 bottom
C209  470P_0402_50V7K  [C_0402]  126.96 85.24 90 bottom
CA1  220P_0402_50V8J  [C_0402]  389.58 15.05 90 bottom
CA2  680P_0402_50V7K  [C_0402]  394.24 23 90 bottom
CA3  680P_0402_50V7K  [C_0402]  394.24 25.69 270 bottom
CA4  220P_0402_50V8J  [C_0402]  389.58 17.08 90 bottom
CA8  0.1U_0201_10V6K  [C_0201]  383.32 28.84 0 top
CA9  10U_0603_10V6M  [C_0603]  383.55 30.75 0 top
CA10  0.1U_0201_10V6K  [C_0201]  376.76 19.23 270 top
CA12  680P_0402_50V7K  [C_0402]  392.5 15.97 270 bottom
CA13  680P_0402_50V7K  [C_0402]  392.5 17.72 90 bottom
CA19  1000P_0402_50V7K  [C_0402]  350.01 21.95 0 top
CA22  1000P_0402_50V7K  [C_0402]  346.16 21.9 0 top
CA23  1000P_0402_50V7K  [C_0402]  345.3 21.9 180 top
CA24  1000P_0402_50V7K  [C_0402]  349.15 21.95 180 top
CA25  10U_0603_10V6M  [C_0603]  388.25 23.89 180 top
CA27  0.1U_0201_25V6K  [C_0201]  387.75 26.68 180 top
CA28  0.1U_0201_25V6K  [C_0201]  387.75 25.8 180 top
CA29  1U_0201_6.3V6K  [C_0201]  385.49 17.54 180 top
CA31  1U_0201_6.3V6M  [C_0201]  376.95 28.69 270 top
CA33  10P_0402_50V8J  [C_0402]  377.73 17.02 90 top
CA35  2.2U_0402_6.3V6M  [C_0402]  386.27 30.08 270 bottom
CA41  0.1U_0201_25V6K  [C_0201]  391.49 19.48 270 bottom
CA43  10U_0603_10V6M  [C_0603]  386.85 29.1 0 top
CA44  10U_0603_10V6M  [C_0603]  386.85 27.83 0 top
CA45  0.1U_0201_10V6K  [C_0201]  382.34 25.96 270 bottom
CA46  10U_0603_10V6M  [C_0603]  381.2 31.49 90 top
CA47  0.1U_0201_10V6K  [C_0201]  380.31 25.83 270 bottom
CA48  10U_0603_10V6M  [C_0603]  381.05 30.41 0 top
CA49  1U_0201_6.3V6K  [C_0201]  387.21 19.64 180 top
CA51  10U_0603_10V6M  [C_0603]  384.82 29.62 270 top
CA52  10U_0603_10V6M  [C_0603]  383.49 16.21 90 top
CA53  10U_0603_10V6M  [C_0603]  381.07 16.46 90 top
CA54  68P_0402_50V8J  [C_0402]  374.8 22.24 180 top
CA55  0.1U_0201_10V6K  [C_0201]  377.37 25.4 90 top
CA56  10U_0603_10V6M  [C_0603]  378.14 27.39 90 top
CA57  0.1U_0201_10V6K  [C_0201]  382.56 15.38 0 top
CA58  10U_0603_10V6M  [C_0603]  382.15 14.37 0 top
CA59  10U_0603_10V6M  [C_0603]  378.72 32.78 0 top
CA60  0.1U_0201_10V6K  [C_0201]  378.88 31.89 0 top
CA61  10U_0603_10V6M  [C_0603]  376.76 20.14 90 top
CA63  12P_0402_50V8J  [C_0402]  375.83 30.66 270 top
CA64  68P_0402_50V8J  [C_0402]  376.73 30.66 270 top
CA65  12P_0402_50V8J  [C_0402]  374.72 17.59 90 top
CA66  68P_0402_50V8J  [C_0402]  373.83 17.59 90 top
CA67  12P_0402_50V8J  [C_0402]  392.17 13.73 0 bottom
CA68  68P_0402_50V8J  [C_0402]  392.17 12.84 0 bottom
CA69  33P_0402_50V8J  [C_0402]  382.16 17.55 270 top
CA73  2P_0402_50V8C  [C_0402]  117.63 45.05 180 top
CA74  2P_0402_50V8C  [C_0402]  119.97 42.86 180 top
CA76  2P_0402_50V8C  [C_0402]  120.01 43.75 180 top
CA224  330P_0402_50V8J  [C_0402]  386.46 21.48 0 bottom
CA225  330P_0402_50V8J  [C_0402]  386.46 20.59 0 bottom
CA226  0.1U_0201_25V6K  [C_0201]  374.83 24.65 180 top
CA227  100P_0402_50V8J  [C_0402]  389.46 26.07 0 bottom
CA228  100P_0402_50V8J  [C_0402]  389.56 27.94 0 top
CA232  1U_0201_6.3V6K  [C_0201]  385.49 16.91 180 top
CA233  1U_0201_6.3V6K  [C_0201]  387.21 19.06 180 top
CC28  0.1U_0402_25V6  [C_0402]  243.54 13.47 180 bottom
CC29  0.1U_0402_25V6  [C_0402]  245.84 21.34 90 bottom
CC32  0.1U_0402_25V6  [C_0402]  243.3 21.47 90 bottom
CC33  0.1U_0402_25V6  [C_0402]  232.17 14.68 0 top
CC34  0.22U_0402_16V7K  [C_0402]  253.38 75.24 90 top
CC35  0.22U_0402_16V7K  [C_0402]  252.49 75.24 90 top
CC36  0.22U_0402_16V7K  [C_0402]  251.28 77.19 90 top
CC37  0.22U_0402_16V7K  [C_0402]  252.18 77.19 90 top
CC38  0.22U_0402_16V7K  [C_0402]  250.94 75.24 90 top
CC39  0.22U_0402_16V7K  [C_0402]  250.05 75.24 90 top
CC40  0.22U_0402_16V7K  [C_0402]  248.89 77.19 90 top
CC41  0.22U_0402_16V7K  [C_0402]  249.78 77.19 90 top
CC42  0.22U_0402_16V7K  [C_0402]  248.62 75.24 90 top
CC43  0.22U_0402_16V7K  [C_0402]  247.73 75.24 90 top
CC44  0.22U_0402_16V7K  [C_0402]  247.51 77.19 90 top
CC45  0.22U_0402_16V7K  [C_0402]  246.62 77.19 90 top
CC46  0.22U_0402_16V7K  [C_0402]  246.38 75.24 90 top
CC47  0.22U_0402_16V7K  [C_0402]  245.5 75.24 90 top
CC48  0.22U_0402_16V7K  [C_0402]  244.41 77.19 90 top
CC49  0.22U_0402_16V7K  [C_0402]  245.3 77.19 90 top
CC50  0.22U_0402_16V7K  [C_0402]  243.35 75.24 90 top
CC51  0.22U_0402_16V7K  [C_0402]  244.24 75.24 90 top
CC52  0.22U_0402_16V7K  [C_0402]  243.06 77.19 90 top
CC53  0.22U_0402_16V7K  [C_0402]  242.17 77.19 90 top
CC54  0.22U_0402_16V7K  [C_0402]  241.03 75.24 90 top
CC55  0.22U_0402_16V7K  [C_0402]  241.92 75.24 90 top
CC56  0.22U_0402_16V7K  [C_0402]  240.87 77.19 90 top
CC57  0.22U_0402_16V7K  [C_0402]  239.98 77.19 90 top
CC58  0.22U_0402_16V7K  [C_0402]  239.83 75.24 90 top
CC59  0.22U_0402_16V7K  [C_0402]  238.94 75.24 90 top
CC60  0.22U_0402_16V7K  [C_0402]  237.77 77.19 90 top
CC61  0.22U_0402_16V7K  [C_0402]  238.66 77.19 90 top
CC62  0.22U_0402_16V7K  [C_0402]  237.51 75.24 90 top
CC63  0.22U_0402_16V7K  [C_0402]  236.62 75.24 90 top
CC64  0.22U_0402_16V7K  [C_0402]  235.41 77.19 90 top
CC65  0.22U_0402_16V7K  [C_0402]  236.3 77.19 90 top
CC81  22U_0603_6.3V6M  [C_0603]  219.09 35.7 180 bottom
CC82  22U_0603_6.3V6M  [C_0603]  219.31 61.48 180 bottom
CC83  22U_0603_6.3V6M  [C_0603]  219.17 53.62 180 bottom
CC84  22U_0603_6.3V6M  [C_0603]  219.09 37.61 180 bottom
CC161  10U_0402_6.3V6M  [C_0402]  218.84 49.93 180 bottom
CC163  10U_0402_6.3V6M  [C_0402]  218.84 45.61 180 bottom
CC164  10U_0402_6.3V6M  [C_0402]  218.84 40.91 180 bottom
CC165  10U_0402_6.3V6M  [C_0402]  219.05 57.56 180 bottom
CC166  10U_0402_6.3V6M  [C_0402]  218.84 39.26 180 bottom
CC167  10U_0402_6.3V6M  [C_0402]  219.05 56.04 180 bottom
CC168  10U_0402_6.3V6M  [C_0402]  218.84 42.43 180 bottom
CC170  10U_0402_6.3V6M  [C_0402]  218.84 51.83 180 bottom
CC171  10U_0402_6.3V6M  [C_0402]  218.84 43.96 180 bottom
CC172  10U_0402_6.3V6M  [C_0402]  218.84 47.89 180 bottom
CC185  10U_0402_6.3V6M  [C_0402]  219.15 59.87 180 bottom
CC186  1U_0201_6.3V6M  [C_0201]  263.84 65.55 0 top
CC187  10U_0603_6.3V6M  [C_0603]  249.88 60.97 270 bottom
CC188  10U_0603_6.3V6M  [C_0603]  248.61 61.36 270 bottom
CC189  10U_0603_6.3V6M  [C_0603]  247.41 61.36 270 bottom
CC191  1U_0201_6.3V6M  [C_0201]  270.24 69.86 180 top
CC192  1U_0201_6.3V6M  [C_0201]  262.01 68.57 270 top
CC193  1U_0201_10V6M  [C_0201]  270.41 68.91 180 top
CC194  1U_0201_10V6M  [C_0201]  270.41 67.96 180 top
CC195  1U_0201_6.3V6M  [C_0201]  263.84 64.99 0 top
CC209  1U_0201_6.3V6M  [C_0201]  239.2 37.86 0 bottom
CC210  1U_0201_6.3V6M  [C_0201]  241.12 60.29 270 bottom
CC269  0.1U_0402_25V6  [C_0402]  236.57 14.81 270 top
CC272  10U_0603_6.3V6M  [C_0603]  246.2 61.36 270 bottom
CC300  100P_0402_50V8J  [C_0402]  254.35 21 270 top
CC301  100P_0402_50V8J  [C_0402]  220.4 68.38 180 bottom
CC302  0.1U_0201_25V6K  [C_0201]  119.77 56.09 270 top
CC303  0.1U_0201_25V6K  [C_0201]  241.76 22.75 180 bottom
CC304  0.1U_0201_25V6K  [C_0201]  237.92 21.57 90 bottom
CC305  0.1U_0201_25V6K  [C_0201]  235.34 17.19 90 bottom
CC306  0.1U_0402_25V6  [C_0402]  241.25 20.7 90 bottom
CC307  0.1U_0402_25V6  [C_0402]  235.84 13.6 0 bottom
CC308  0.1U_0402_25V6  [C_0402]  240.33 21.47 90 bottom
CC310  0.1U_0201_10V6K  [C_0201]  123.96 43.23 270 bottom
CC311  0.1U_0201_10V6K  [C_0201]  148.16 49.46 270 bottom
CC318  33P_0402_50V8J  [C_0402]  119.91 35.62 180 top
CC319  33P_0402_50V8J  [C_0402]  113.33 33.29 180 top
CC320  33P_0402_50V8J  [C_0402]  106.12 23.56 90 top
CC322  2.2P_0402_50V8C  [C_0402]  163.1 37.06 180 bottom
CC323  0.1U_0402_25V6  [C_0402]  274.31 68.16 0 bottom
CC324  0.1U_0402_25V6  [C_0402]  252.49 21.05 270 top
CC325  33P_0402_50V8J  [C_0402]  266.9 14.32 270 bottom
CC327  2.2P_0402_50V8C  [C_0402]  119.91 43.45 180 bottom
CC328  2.2P_0402_50V8C  [C_0402]  136 33.24 270 bottom
CC329  0.1U_0201_10V6K  [C_0201]  119.07 45.44 90 bottom
CC330  0.1U_0201_10V6K  [C_0201]  149.08 51.2 180 bottom
CC331  0.1U_0201_10V6K  [C_0201]  145.1 47.79 270 bottom
CC332  0.1U_0201_10V6K  [C_0201]  146.66 46.55 180 bottom
CC333  22U_0603_6.3V6M  [C_0603]  262.9 67.77 90 top
CC334  0.1U_0402_25V6  [C_0402]  239.74 37.1 180 bottom
CC335  22U_0603_6.3V6M  [C_0603]  264.11 69.17 270 top
CC336  0.1U_0402_25V6  [C_0402]  239.15 21.06 90 top
CC337  0.1U_0402_25V6  [C_0402]  258.32 13.67 0 top
CC338  0.1U_0402_25V6  [C_0402]  258.66 16.27 180 top
CC568  22U_0603_6.3V6M  [C_0603]  165.77 37.66 0 bottom
CC569  22U_0603_6.3V6M  [C_0603]  269.35 66.79 0 top
CD1  1U_0201_10V6M  [C_0201]  168.97 88.57 90 bottom
CD2  1U_0201_10V6M  [C_0201]  169.86 88.57 90 bottom
CD3  10U_0603_6.3V6M  [C_0603]  170.94 88.37 90 bottom
CD4  10U_0603_6.3V6M  [C_0603]  172.16 88.41 90 bottom
CD5  0.1U_0402_10V6K  [C_0402]  167.08 42.23 90 bottom
CD6  10U_0603_6.3V6M  [C_0603]  184.73 39.91 270 bottom
CD7  10U_0603_6.3V6M  [C_0603]  184.68 29.26 90 bottom
CD8  10U_0603_6.3V6M  [C_0603]  170.6 33.57 180 bottom
CD9  10U_0603_6.3V6M  [C_0603]  170.47 23.89 180 bottom
CD10  10U_0603_6.3V6M  [C_0603]  184.62 72.99 90 bottom
CD11  10U_0603_6.3V6M  [C_0603]  170.32 67.32 180 bottom
CD12  10U_0603_6.3V6M  [C_0603]  184.86 18.53 90 bottom
CD13  10U_0603_6.3V6M  [C_0603]  170.57 75.71 180 bottom
CD14  330U_D2_2V_Y  [C_D2]  224.48 57.14 90 bottom
CD15  0.1U_0201_10V6K  [C_0201]  170.51 43.1 270 bottom
CD16  0.1U_0402_10V6K  [C_0402]  164.38 57.78 90 bottom
CD17  1U_0201_10V6M  [C_0201]  170.19 53.23 180 bottom
CD18  1U_0201_10V6M  [C_0201]  166.82 46.94 90 bottom
CD19  1U_0201_10V6M  [C_0201]  170.19 55.39 180 bottom
CD20  1U_0201_10V6M  [C_0201]  184.29 52.59 90 bottom
CD21  1U_0201_10V6M  [C_0201]  170.19 52.08 180 bottom
CD22  1U_0201_10V6M  [C_0201]  171.02 46.94 90 bottom
CD23  1U_0201_10V6M  [C_0201]  184.35 44.29 270 bottom
CD24  1U_0201_10V6M  [C_0201]  184.17 47.32 0 bottom
CD25  0.022U_0402_16V7K  [C_0402]  169.41 57.78 90 bottom
CD26  0.1U_0402_10V6K  [C_0402]  166.89 58.47 270 bottom
CD27  10U_0603_6.3V6M  [C_0603]  177.16 89.49 0 bottom
CD28  0.1U_0402_10V6K  [C_0402]  184.33 58.24 90 bottom
CD29  2.2U_0402_6.3V6M  [C_0402]  184.7 57.39 270 bottom
CD30  1U_0201_10V6M  [C_0201]  177.39 88.47 0 bottom
CD31  1U_0201_10V6M  [C_0201]  177.39 90.57 0 bottom
CD32  0.1U_0402_10V6K  [C_0402]  170.63 79.4 270 bottom
CD33  2.2U_0603_10V7K  [C_0603]  169.53 79.65 270 bottom
CD34  0.1U_0402_25V6  [C_0402]  152.85 16.44 270 bottom
CD35  10U_0603_6.3V6M  [C_0603]  183.75 91.34 0 top
CD36  1U_0201_10V6M  [C_0201]  184.38 89.11 0 top
CD37  1U_0201_10V6M  [C_0201]  183.22 88.98 180 top
CD38  10U_0603_6.3V6M  [C_0603]  183.73 90.14 0 top
CD39  10U_0603_6.3V6M  [C_0603]  184.7 77.14 90 top
CD40  10U_0603_6.3V6M  [C_0603]  169.96 28.87 180 bottom
CD41  10U_0603_6.3V6M  [C_0603]  169.68 39.91 270 bottom
CD42  10U_0603_6.3V6M  [C_0603]  184.49 34.3 270 top
CD43  10U_0603_6.3V6M  [C_0603]  184.75 23.57 270 top
CD44  10U_0603_6.3V6M  [C_0603]  170.39 72.38 180 bottom
CD45  10U_0603_6.3V6M  [C_0603]  184.66 68.87 90 top
CD46  10U_0603_6.3V6M  [C_0603]  170.6 19.37 180 bottom
CD47  330U_D2_2V_Y  [C_D2]  150.11 9.67 270 top
CD48  0.1U_0201_10V6K  [C_0201]  169.62 43.1 270 bottom
CD49  1U_0201_10V6M  [C_0201]  170.19 54.37 180 bottom
CD50  1U_0201_10V6M  [C_0201]  184.28 50.73 90 top
CD51  1U_0201_10V6M  [C_0201]  184.22 47.16 270 top
CD52  1U_0201_10V6M  [C_0201]  167.84 46.94 90 bottom
CD53  1U_0201_10V6M  [C_0201]  170.19 50.94 180 bottom
CD54  1U_0201_10V6M  [C_0201]  170.13 46.94 90 bottom
CD55  1U_0201_10V6M  [C_0201]  167.08 44.8 270 bottom
CD56  1U_0201_10V6M  [C_0201]  184.3 56.69 270 top
CD57  10U_0603_6.3V6M  [C_0603]  176.97 89.87 0 top
CD58  1U_0201_10V6M  [C_0201]  177.33 91.07 0 top
CD59  1U_0201_10V6M  [C_0201]  177.39 88.79 0 top
CD60  0.1U_0402_10V6K  [C_0402]  166.25 60.29 90 bottom
CD61  2.2U_0402_6.3V6M  [C_0402]  167.2 60.29 90 bottom
CD62  0.1U_0402_10V6K  [C_0402]  180.69 89.09 90 top
CD63  2.2U_0603_10V7K  [C_0603]  181.74 88.91 90 top
CD64  1U_0201_10V6M  [C_0201]  186.86 89.13 90 bottom
CD65  1U_0201_10V6M  [C_0201]  187.75 89.13 90 bottom
CD66  10U_0603_6.3V6M  [C_0603]  188.83 88.96 90 bottom
CD67  10U_0603_6.3V6M  [C_0603]  190.1 88.96 90 bottom
CD68  10U_0603_6.3V6M  [C_0603]  184.72 23.34 270 bottom
CD69  10U_0603_6.3V6M  [C_0603]  198.89 18.68 0 bottom
CD70  10U_0603_6.3V6M  [C_0603]  184.78 34.67 90 bottom
CD71  10U_0603_6.3V6M  [C_0603]  184.45 77.87 90 bottom
CD72  10U_0603_6.3V6M  [C_0603]  199.15 28.97 90 bottom
CD73  10U_0603_6.3V6M  [C_0603]  199.27 72.53 0 bottom
CD74  10U_0603_6.3V6M  [C_0603]  198.64 39.58 0 bottom
CD75  10U_0603_6.3V6M  [C_0603]  184.8 67.24 270 bottom
CD76  330U_D2_2V_Y  [C_D2]  224.09 38.21 270 bottom
CD77  0.1U_0402_10V6K  [C_0402]  202.28 56.03 0 bottom
CD78  0.1U_0201_10V6K  [C_0201]  198.62 42.12 0 bottom
CD79  1U_0201_10V6M  [C_0201]  184.29 50.15 270 bottom
CD80  1U_0201_10V6M  [C_0201]  184.99 42.51 270 bottom
CD81  1U_0201_10V6M  [C_0201]  198.42 46.98 0 bottom
CD82  1U_0201_10V6M  [C_0201]  198.64 43.21 0 bottom
CD83  1U_0201_10V6M  [C_0201]  198.75 50.43 0 bottom
CD84  1U_0201_10V6M  [C_0201]  184.29 54.54 270 bottom
CD85  1U_0201_10V6M  [C_0201]  198.63 55.89 0 bottom
CD86  1U_0201_10V6M  [C_0201]  184.67 45.48 90 bottom
CD87  0.022U_0402_16V7K  [C_0402]  206.16 57.11 0 bottom
CD88  0.1U_0402_10V6K  [C_0402]  204.44 56.21 0 bottom
CD89  0.1U_0402_10V6K  [C_0402]  204.39 55.07 180 bottom
CD90  0.1U_0402_10V6K  [C_0402]  205.46 54.37 0 bottom
CD91  10U_0603_6.3V6M  [C_0603]  203.32 78.86 270 bottom
CD92  1U_0201_10V6M  [C_0201]  202.24 78.8 270 bottom
CD93  1U_0201_10V6M  [C_0201]  201.35 78.8 270 bottom
CD94  0.1U_0402_10V6K  [C_0402]  202.11 59.41 270 bottom
CD95  2.2U_0402_6.3V6M  [C_0402]  201.22 59.41 270 bottom
CD96  0.1U_0402_10V6K  [C_0402]  207.38 59.67 270 bottom
CD97  0.1U_0402_10V6K  [C_0402]  203.89 59.41 270 bottom
CD98  0.1U_0402_10V6K  [C_0402]  185.11 88.71 90 bottom
CD99  2.2U_0603_10V7K  [C_0603]  184.04 88.48 90 bottom
CD100  1U_0201_10V6M  [C_0201]  195.74 88.53 0 top
CD101  1U_0201_10V6M  [C_0201]  194.13 88.75 90 top
CD102  10U_0603_6.3V6M  [C_0603]  195.54 89.62 0 top
CD103  10U_0603_6.3V6M  [C_0603]  195.55 90.82 0 top
CD104  10U_0603_6.3V6M  [C_0603]  184.56 73.12 90 top
CD105  10U_0603_6.3V6M  [C_0603]  184.68 28.89 270 top
CD106  10U_0603_6.3V6M  [C_0603]  184.79 19.68 90 top
CD107  10U_0603_6.3V6M  [C_0603]  198.89 74.82 0 bottom
CD108  10U_0603_6.3V6M  [C_0603]  198.89 34.06 270 bottom
CD109  10U_0603_6.3V6M  [C_0603]  198.51 44.34 0 bottom
CD110  10U_0603_6.3V6M  [C_0603]  199.19 67.2 0 bottom
CD111  10U_0603_6.3V6M  [C_0603]  199.02 23.38 270 bottom
CD112  330U_D2_2V_Y  [C_D2]  162.66 90.57 180 bottom
CD113  0.1U_0201_10V6K  [C_0201]  184.92 42.32 270 top
CD114  1U_0201_10V6M  [C_0201]  184.67 54.47 270 top
CD115  1U_0201_10V6M  [C_0201]  184.54 43.93 270 top
CD116  1U_0201_10V6M  [C_0201]  198.63 57.42 0 bottom
CD117  1U_0201_10V6M  [C_0201]  184.99 45.42 270 top
CD118  1U_0201_10V6M  [C_0201]  184.97 49.53 270 top
CD119  1U_0201_10V6M  [C_0201]  198.75 49.54 0 bottom
CD120  1U_0201_10V6M  [C_0201]  198.5 45.48 0 bottom
CD121  1U_0201_10V6M  [C_0201]  198.75 51.96 0 bottom
CD122  10U_0603_6.3V6M  [C_0603]  188.09 89.78 90 top
CD123  1U_0201_10V6M  [C_0201]  187.15 89.91 90 top
CD124  1U_0201_10V6M  [C_0201]  186.25 89.91 90 top
CD125  0.1U_0402_10V6K  [C_0402]  184.6 59.15 270 top
CD126  2.2U_0402_6.3V6M  [C_0402]  184.65 60.71 90 top
CD127  0.1U_0402_10V6K  [C_0402]  199.21 87.7 90 top
CD128  2.2U_0603_10V7K  [C_0603]  198.13 87.71 90 top
CE3  2200P_0402_50V7K  [C_0402]  129.97 72.67 180 bottom
CE4  2200P_0402_50V7K  [C_0402]  129.84 69.62 180 bottom
CE8  0.047U_0201_10V6K  [C_0201]  144.9 62.55 0 top
CE10  1U_0201_10V6M  [C_0201]  123.97 77.75 0 top
CE11  0.1U_0201_10V6K  [C_0201]  134.73 80.77 90 bottom
CE12  2.2U_0402_6.3V6M  [C_0402]  125.88 79.4 0 top
CE13  0.1U_0201_10V6K  [C_0201]  139.12 78.8 90 bottom
CE14  1U_0201_10V6M  [C_0201]  133.28 72.42 180 bottom
CE15  0.1U_0201_10V6K  [C_0201]  139.82 69.08 270 bottom
CE16  10U_0402_6.3V6M  [C_0402]  128.81 69.67 90 top
CE17  22U_0603_6.3V6M  [C_0603]  129.86 76.89 270 top
CE18  0.1U_0201_10V6K  [C_0201]  130.76 76 270 top
CE19  0.1U_0201_10V6K  [C_0201]  139.27 69.08 270 bottom
CE20  0.1U_0201_10V6K  [C_0201]  133.3 74.33 180 bottom
CE21  0.1U_0201_10V6K  [C_0201]  126.99 70.36 90 top
CE22  0.1U_0201_10V6K  [C_0201]  126.27 70.23 180 top
CE23  0.1U_0201_10V6K  [C_0201]  138.97 74.61 0 bottom
CE24  2200P_0402_50V7K  [C_0402]  138.35 81.69 180 top
CE25  0.1U_0201_10V6K  [C_0201]  144.7 70.79 0 bottom
CE26  2200P_0402_50V7K  [C_0402]  140.38 81.69 180 top
CE27  2200P_0402_50V7K  [C_0402]  142.16 81.69 180 top
CE28  10P_0402_50V8J  [C_0402]  132.53 82.55 180 top
CE29  12P_0402_50V8J  [C_0402]  133.4 82.55 0 top
CE30  1U_0201_10V6M  [C_0201]  152.27 74.31 0 bottom
CE31  1U_0201_10V6M  [C_0201]  139.71 78.78 90 bottom
CE35  100P_0402_50V8J  [C_0402]  245.13 60.89 270 bottom
CE36  0.1U_0201_25V6K  [C_0201]  132.47 62.43 90 top
CE38  0.1U_0201_25V6K  [C_0201]  142.08 83.39 90 top
CE39  100P_0402_50V8J  [C_0402]  162.3 101.91 0 bottom
CE40  4700P_0402_25V7K  [C_0402]  149.25 64.4 180 bottom
CE46  100P_0402_50V8J  [C_0402]  316.54 34.59 90 bottom
CE47  4700P_0402_25V7K  [C_0402]  134.22 61.63 180 top
CE52  0.1U_0201_25V6K  [C_0201]  154.32 67.48 180 bottom
CE53  0.1U_0201_25V6K  [C_0201]  155.01 63.05 0 bottom
CE54  10P_0402_50V8J  [C_0402]  130.49 78.67 180 top
CE57  33P_0402_50V8J  [C_0402]  144.46 66.47 90 top
CE59  12P_0402_50V8J  [C_0402]  151.77 67.66 180 bottom
CE60  68P_0402_50V8J  [C_0402]  151.77 66.64 180 bottom
CE61  68P_0402_50V8J  [C_0402]  135.46 63.73 90 top
CE62  4700P_0402_25V7K  [C_0402]  149.38 61.74 180 bottom
CE63  1U_0201_10V6M  [C_0201]  145.79 89.23 270 top
CE64  0.1U_0201_25V6K  [C_0201]  143.95 82.61 0 top
CE65  22P_0402_50V8J  [C_0402]  145.81 82.51 270 top
CE66  0.1U_0201_25V6K  [C_0201]  137.03 67.39 270 top
CE270  2200P_0402_50V7K  [C_0402]  139.34 83.2 180 top
CE272  100P_0402_50V8J  [C_0402]  146.3 17.96 0 top
CE339  100P_0402_50V8J  [C_0402]  305.18 30.62 0 top
CE340  0.1U_0201_25V6K  [C_0201]  156.92 69.81 270 bottom
CE341  0.1U_0201_25V6K  [C_0201]  159.97 78.3 90 bottom
CE342  0.1U_0201_25V6K  [C_0201]  163.55 74.06 0 bottom
CE343  1U_0201_10V6M  [C_0201]  155.78 74.87 90 bottom
CH4  15P_0402_50V8J  [C_0402]  128.28 19.37 180 top
CH5  15P_0402_50V8J  [C_0402]  125.6 19.36 0 top
CH9  0.1U_0201_10V6K  [C_0201]  123.01 22.71 90 bottom
CH10  0.1U_0201_25V6K  [C_0201]  123.2 55.87 270 top
CH13  15P_0402_50V8J  [C_0402]  139.68 56.06 0 top
CH14  15P_0402_50V8J  [C_0402]  138.76 55.49 180 top
CH20  1U_0201_6.3V6M  [C_0201]  144.54 47.79 270 bottom
CH21  1U_0201_6.3V6M  [C_0201]  132.76 40.72 180 bottom
CH22  4.7U_0402_6.3V6M  [C_0402]  128.15 41.59 90 bottom
CH29  1U_0201_6.3V6M  [C_0201]  146.69 54.44 270 bottom
CH30  4.7U_0402_6.3V6M  [C_0402]  118.98 49.53 180 top
CH31  1U_0201_6.3V6M  [C_0201]  147.39 49.53 270 bottom
CH32  4.7U_0402_6.3V6M  [C_0402]  145.67 52.08 0 bottom
CH33  1U_0201_6.3V6M  [C_0201]  125.55 25.88 90 bottom
CH34  1U_0201_6.3V6M  [C_0201]  146.5 39.41 90 bottom
CH35  1U_0201_6.3V6M  [C_0201]  119.53 24.53 180 top
CH36  1U_0201_6.3V6M  [C_0201]  134.64 37.1 180 bottom
CH37  1U_0201_6.3V6M  [C_0201]  125.78 46.98 90 bottom
CH38  0.1U_0201_10V6K  [C_0201]  138.75 38.74 0 bottom
CH40  1U_0201_6.3V6M  [C_0201]  119.35 20.78 90 top
CH41  1U_0201_6.3V6M  [C_0201]  122.1 20.77 90 top
CH44  0.1U_0201_10V6K  [C_0201]  137.95 40.58 135 bottom
CH45  47U_0603_6.3V6M  [C_0603]  144.21 59.9 270 top
CH46  1U_0201_6.3V6M  [C_0201]  145.67 51.07 0 bottom
CH47  22U_0603_6.3V6M  [C_0603]  145.02 39.19 90 bottom
CH62  0.1U_0201_10V6K  [C_0201]  132.46 31.34 270 bottom
CH63  0.1U_0201_10V6K  [C_0201]  123.75 23.56 270 bottom
CH64  0.1U_0201_10V6K  [C_0201]  135.96 31.17 270 bottom
CH65  0.1U_0201_10V6K  [C_0201]  124.66 23.56 270 bottom
CH66  0.1U_0201_10V6K  [C_0201]  136.92 33.01 270 bottom
CH67  0.1U_0201_10V6K  [C_0201]  119.62 47.13 180 bottom
CH68  0.1U_0201_10V6K  [C_0201]  119.62 22.87 180 top
CH266  0.01U_0402_16V7K  [C_0402]  122.4 18.49 0 top
CH267  1U_0201_6.3V6M  [C_0201]  144.3 21.86 180 top
CH268  47P_0402_50V8J  [C_0402]  116.94 43.27 0 bottom
CH270  0.1U_0201_10V6K  [C_0201]  101.53 27.69 180 bottom
CH321  33P_0402_50V8J  [C_0402]  100.49 26.39 0 bottom
CH322  33P_0402_50V8J  [C_0402]  121.22 24.24 270 bottom
CH323  4.7U_0402_6.3V6M  [C_0402]  120.9 47.16 90 bottom
CH324  22U_0603_6.3V6M  [C_0603]  144.47 20.37 180 top
CH340  0.1U_0201_25V6K  [C_0201]  116.51 24.17 0 top
CH341  0.033U_0402_16V7  [C_0402]  111.63 37 180 top
CH342  0.033U_0402_16V7  [C_0402]  108.62 13.36 270 bottom
CH343  0.033U_0402_16V7  [C_0402]  119.85 29.38 90 bottom
CH344  0.033U_0402_16V7  [C_0402]  117.6 30.69 180 bottom
CH345  0.033U_0402_16V7  [C_0402]  117.38 29.21 180 bottom
CH346  0.033U_0402_16V7  [C_0402]  117.57 27.37 90 top
CH347  0.033U_0402_16V7  [C_0402]  121.33 29.69 90 bottom
CH348  0.033U_0402_16V7  [C_0402]  110.72 32.43 0 top
CH349  0.047U_0201_10V6K  [C_0201]  114.27 31.74 180 top
CH350  0.047U_0201_10V6K  [C_0201]  111.03 33.07 90 bottom
CH555  1U_0201_6.3V6M  [C_0201]  144.3 21.26 180 top
CH559  4.7U_0402_6.3V6M  [C_0402]  118.98 50.43 180 top
CH560  22U_0603_6.3V6M  [C_0603]  144.3 19.15 180 top
CI1  150U_B2_6.3VM_R35M  [C_B2]  390.8 33.34 90 top
CI3  10U_0402_6.3V6M  [C_0402]  388.34 33.56 270 top
CI13  0.1U_0201_10V6K  [C_0201]  114.02 155.81 270 top
CI14  10U_0402_6.3V6M  [C_0402]  388.5 59.46 270 top
CI16  0.1U_0201_10V6K  [C_0201]  113 155.81 270 top
CI32  150U_B2_6.3VM_R35M  [C_B2]  391.11 59.68 90 top
CI60  0.1U_0201_16V6K  [C_0201]  378.81 58.24 90 bottom
CI61  0.01U_0402_16V7K  [C_0402]  382.49 50.52 270 bottom
CI62  0.1U_0201_10V6K  [C_0201]  376.47 51.46 180 bottom
CI63  0.1U_0201_10V6K  [C_0201]  385.74 53.11 180 bottom
CI64  0.1U_0201_10V6K  [C_0201]  385.74 54 180 bottom
CI65  0.1U_0201_10V6K  [C_0201]  376.47 52.35 180 bottom
CI66  0.1U_0201_10V6K  [C_0201]  375.56 53.24 0 bottom
CI67  0.1U_0201_10V6K  [C_0201]  375.56 54.13 0 bottom
CI68  0.01U_0402_16V7K  [C_0402]  386.97 40.24 270 bottom
CI69  0.1U_0201_16V6K  [C_0201]  382.49 47.58 90 bottom
CI70  0.1U_0201_10V6K  [C_0201]  380.41 42.19 180 bottom
CI71  0.1U_0201_10V6K  [C_0201]  389.51 41.65 180 bottom
CI72  0.1U_0201_10V6K  [C_0201]  380.41 43.08 180 bottom
CI73  0.1U_0201_10V6K  [C_0201]  389.51 42.66 180 bottom
CI74  0.1U_0201_10V6K  [C_0201]  379.5 43.97 0 bottom
CI75  0.1U_0201_10V6K  [C_0201]  379.5 44.86 0 bottom
CI76  10U_0402_6.3V6M  [C_0402]  115.83 154.82 90 top
CI77  150U_B2_6.3VM_R35M  [C_B2]  125.5 159.6 180 top
CL1  0.1U_0201_10V6K  [C_0201]  151.02 134.7 270 top
CL2  0.1U_0201_10V6K  [C_0201]  151.91 134.7 270 top
CL3  10U_0402_6.3V6M  [C_0402]  163.32 137.3 0 top
CL4  0.1U_0201_10V6K  [C_0201]  155.72 134.7 270 top
CL5  0.1U_0201_10V6K  [C_0201]  152.8 133.79 90 top
CL6  0.1U_0201_10V6K  [C_0201]  153.69 133.79 90 top
CL7  1U_0201_10V6M  [C_0201]  159.29 137.49 0 top
CL8  22U_0603_6.3V6M  [C_0603]  162.81 138.66 0 top
CL9  0.1U_0201_10V6K  [C_0201]  149.75 135.46 270 top
CL10  0.1U_0201_10V6K  [C_0201]  153.95 142.74 0 bottom
CL11  0.1U_0201_10V6K  [C_0201]  151.8 143.15 270 bottom
CL12  0.1U_0201_10V6K  [C_0201]  156.61 134.7 270 top
CL13  27P_0402_50V8J  [C_0402]  159.05 141.93 270 top
CL14  27P_0402_50V8J  [C_0402]  159.07 142.9 90 top
CL15  0.1U_0201_10V6K  [C_0201]  146.07 139.62 0 top
CL16  0.47U_0201_25V6M  [C_0201]  167.8 170.21 0 top
CL17  0.47U_0201_25V6M  [C_0201]  167.8 168.81 0 top
CL18  470P_0402_50V7K  [C_0402]  133.96 153.25 270 top
CL19  0.1U_0201_10V6K  [C_0201]  134.74 155.03 180 top
CL20  0.47U_0201_25V6M  [C_0201]  167.78 162.57 0 top
CL21  0.47U_0201_25V6M  [C_0201]  167.78 161.3 0 top
CL22  10P_1808_3KV8J  [C_1808]  167.22 155.59 180 bottom
CL28  22U_0603_6.3V6M  [C_0603]  162.68 135.61 0 top
CL199  1U_0201_10V6M  [C_0201]  134.85 153.25 270 top
CL280  0.1U_0201_10V6K  [C_0201]  163.29 134.32 0 top
CLIP1  -  [YDM_DH792_1P-T]  31.2 32.84 180 bottom
CLIP2  -  [YDM_DH792_1P-T]  139.29 60.61 180 top
CMOS1  SHORT PADS~D  [SHORTPADS-NPM]  119.23 18.98 90 top
CN1  10U_0402_6.3V6M  [C_0402]  308.9 23.99 90 bottom
CN2  0.1U_0201_25V6K  [C_0201]  309.83 24.23 90 bottom
CN65  0.22U_0201_6.3V6K  [C_0201]  315.76 29.75 0 bottom
CN66  0.22U_0201_6.3V6K  [C_0201]  315.76 28.86 0 bottom
CN67  0.22U_0201_6.3V6K  [C_0201]  315.76 26.7 0 bottom
CN68  0.22U_0201_6.3V6K  [C_0201]  315.76 25.81 0 bottom
CN69  0.22U_0201_6.3V6K  [C_0201]  315.76 23.78 0 bottom
CN70  0.22U_0201_6.3V6K  [C_0201]  315.76 22.89 0 bottom
CN71  0.22U_0201_6.3V6K  [C_0201]  315.76 20.6 0 bottom
CN72  0.22U_0201_6.3V6K  [C_0201]  315.76 19.71 0 bottom
CN174  10U_0402_6.3V6M  [C_0402]  329.89 32.7 0 bottom
CN175  0.01U_0402_16V7K  [C_0402]  329.25 12.29 0 bottom
CN176  0.01U_0402_16V7K  [C_0402]  329.36 14.53 0 bottom
CN177  0.1U_0201_10V6K  [C_0201]  329.44 15.33 0 bottom
